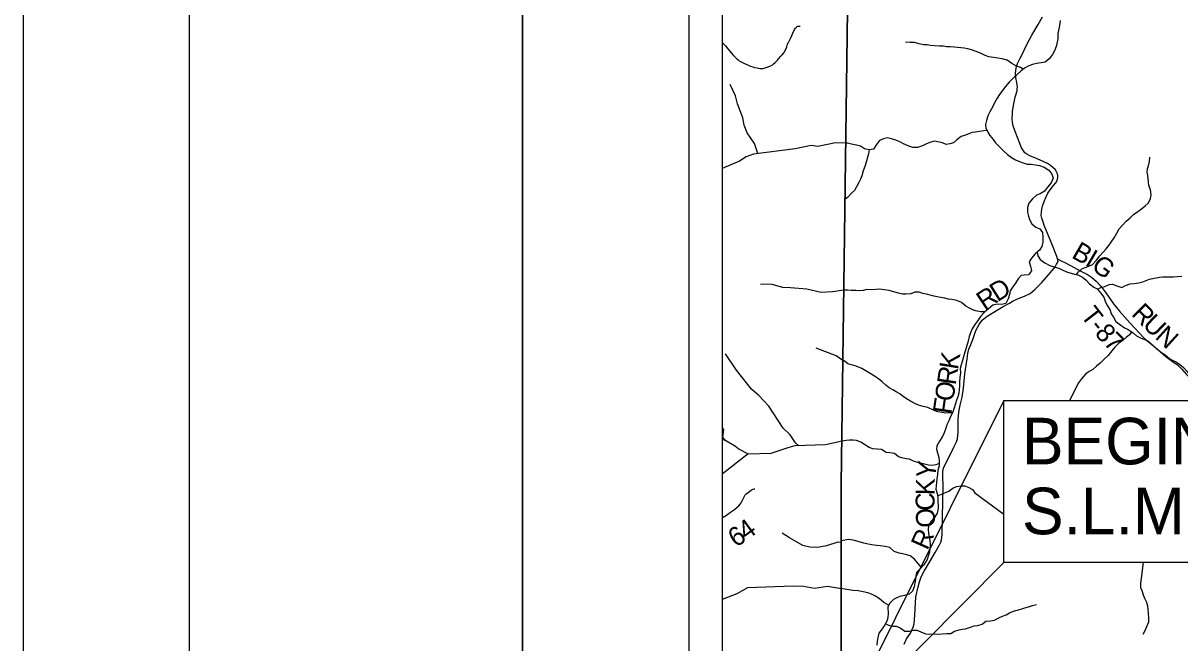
# Model space of a CAD drawing. Extents: x 0 to 34, y 0 to 22.
# Drawn here: x 0 to 3.475, y 18.432 to 20.293 of the extents above; entities that cross this region are included whole.
import ezdxf

# ---------------------------------------------------------------- set-up
doc = ezdxf.new("R2010")
doc.units = 0
for name, color, linetype in [('Default', 7, 'Continuous'), ('GM_X_County_Road', 7, 'Continuous'), ('GM_X_County_Road_Text', 7, 'Continuous'), ('GM_X_Minor_River', 7, 'Continuous'), ('GM_X_Township_Road', 7, 'Continuous'), ('GM_X_Township_Road_Text', 7, 'Continuous'), ('SH_Border', 7, 'Continuous'), ('SH_Cut_Line', 7, 'Continuous'), ('SH_Data', 7, 'Continuous'), ('SH_Text', 7, 'Continuous')]:
    doc.layers.add(name, color=color, linetype=linetype)

msp = doc.modelspace()

# ---------------------------------------------------------------- linework, layer by layer
at = {"layer": 'Default'}
for points in [[(2.4313, 15.0183), (2.4545, 17.2795), (2.4586, 17.7785), (2.4581, 18.1772), (2.4581, 18.1825), (2.4573, 18.9074), (2.4757, 20.2566), (2.4809, 20.6393), (2.4845, 20.9), (2.1, 20.9), (2.1, 14.9328)], [(6.416, 20.9), (2.4845, 20.9), (2.4809, 20.6393), (2.4757, 20.2566), (2.4573, 18.9074), (2.4581, 18.1825), (2.4581, 18.1772), (2.4586, 17.7785), (2.4545, 17.2795), (2.6193, 17.2753), (3.4366, 17.255), (3.467, 17.2465), (3.4629, 17.4891), (3.5442, 17.5398)]]:
    msp.add_lwpolyline(points, dxfattribs=at)
at = {"layer": 'GM_X_County_Road'}
for points in [[(2.9992, 20.1948), (3.0166, 20.2316), (3.0304, 20.257), (3.0492, 20.2896), (3.0625, 20.3124)], [(2.9869, 20.0982), (2.9871, 20.1001), (2.9869, 20.1075), (2.9856, 20.1151), (2.9826, 20.1288), (2.9818, 20.141), (2.9828, 20.1522), (2.9846, 20.1629), (2.9874, 20.1721), (2.9958, 20.1876), (2.9992, 20.1948)], [(2.6466, 18.4282), (2.654, 18.4437), (2.6662, 18.4612), (2.6738, 18.4788), (2.6772, 18.4887), (2.6792, 18.5154), (2.682, 18.5697), (2.6888, 18.5999), (2.6926, 18.6151), (2.6975, 18.6276), (2.7015, 18.6365), (2.7068, 18.6475), (2.7228, 18.674), (2.7397, 18.7033), (2.7529, 18.7265), (2.757, 18.7341), (2.7596, 18.7413), (2.761, 18.7562), (2.7621, 18.8099), (2.7646, 18.8999), (2.7633, 18.9353), (2.7635, 18.9461), (2.7656, 18.9561), (2.769, 18.9658), (2.7791, 18.9848), (2.7966, 19.02), (2.804, 19.0358), (2.8068, 19.0447), (2.8093, 19.0653), (2.8093, 19.0817), (2.8089, 19.1033), (2.8114, 19.1245), (2.8148, 19.1457), (2.8208, 19.17), (2.8251, 19.1965), (2.8295, 19.2395), (2.8359, 19.2848), (2.8386, 19.301), (2.8417, 19.3137), (2.845, 19.3229), (2.853, 19.3428), (2.8628, 19.3703), (2.8722, 19.388), (2.8814, 19.401), (2.8968, 19.4135), (2.9449, 19.4422), (2.9637, 19.4526), (2.9749, 19.4594), (2.9923, 19.4671), (3.0085, 19.4735), (3.0251, 19.4807), (3.0394, 19.4928), (3.0604, 19.5142), (3.0863, 19.5444), (3.1003, 19.5614), (3.1051, 19.5696), (3.1093, 19.5769), (3.108, 19.5852), (3.1059, 19.5921), (3.0907, 19.6302), (3.0688, 19.6833), (3.0606, 19.7072), (3.0591, 19.7153), (3.0594, 19.7252), (3.0606, 19.7346), (3.0627, 19.7435), (3.0672, 19.7573), (3.0726, 19.7697), (3.0787, 19.7822), (3.0858, 19.7926), (3.096, 19.8053), (3.1026, 19.814), (3.1062, 19.8211), (3.1084, 19.8298), (3.109, 19.8353), (3.1077, 19.8409), (3.1051, 19.8468), (3.1013, 19.8529), (3.0937, 19.86), (3.0866, 19.8656), (3.0772, 19.8715), (3.0665, 19.8771), (3.0469, 19.8857), (3.0296, 19.8926), (3.0222, 19.8959), (3.0159, 19.8997), (3.0093, 19.904), (3.0054, 19.9096), (2.9988, 19.9208), (2.9948, 19.9317), (2.9803, 19.9676), (2.9747, 19.9851), (2.9726, 19.9951), (2.9719, 20.0073), (2.9721, 20.0197), (2.9729, 20.0291), (2.9749, 20.0396), (2.9767, 20.0505), (2.981, 20.0706), (2.9861, 20.0904), (2.9869, 20.0982)]]:
    msp.add_lwpolyline(points, dxfattribs=at)
at = {"layer": 'GM_X_Minor_River'}
msp.add_line((2.1783, 18.9994), (2.1, 18.9382), dxfattribs=at)
for points in [[(3.1162, 20.3016), (3.1146, 20.2922), (3.1127, 20.2812), (3.1111, 20.2713), (3.1092, 20.2618), (3.1087, 20.2463), (3.1056, 20.2326), (3.1036, 20.2228), (3.099, 20.2099), (3.0925, 20.1986), (3.0829, 20.1861), (3.0707, 20.1759), (3.0586, 20.1737), (3.0449, 20.1719), (3.0328, 20.169), (3.0199, 20.1645), (3.0081, 20.1585), (2.9971, 20.1495), (2.9875, 20.1404), (2.9749, 20.1283), (2.9624, 20.1159), (2.9517, 20.1034), (2.9414, 20.0895), (2.9333, 20.0789), (2.9265, 20.0679), (2.9188, 20.0543), (2.9123, 20.0407), (2.9046, 20.0271), (2.8988, 20.0146), (2.8942, 20.001), (2.8911, 19.9885), (2.8922, 19.9786), (2.8982, 19.9656), (2.9045, 19.9557), (2.9143, 19.9439), (2.9218, 19.9336), (2.9331, 19.9214), (2.9459, 19.9099), (2.9576, 19.8985), (2.9697, 19.8901), (2.9817, 19.8824), (2.9938, 19.8774), (3.0048, 19.8735), (3.0169, 19.87), (3.0286, 19.87), (3.0415, 19.868), (3.0536, 19.8656), (3.0676, 19.861), (3.0816, 19.8518), (3.091, 19.84), (3.0947, 19.8274), (3.0889, 19.8138), (3.0775, 19.8006), (3.0683, 19.7881), (3.0558, 19.781), (3.0444, 19.7761), (3.0322, 19.7656), (3.0215, 19.7524), (3.0172, 19.7399), (3.0175, 19.7258), (3.0208, 19.7133), (3.0238, 19.703), (3.0306, 19.6908), (3.0422, 19.6809), (3.0547, 19.6751), (3.0626, 19.664), (3.064, 19.65), (3.0632, 19.6356), (3.0608, 19.6227), (3.0532, 19.6114), (3.0402, 19.6004), (3.0292, 19.5872), (3.0226, 19.5759), (3.0267, 19.563), (3.0297, 19.5497), (3.0205, 19.5376), (3.0076, 19.5365), (2.9981, 19.5354), (2.9897, 19.5252), (2.9813, 19.5124), (2.9733, 19.5014), (2.9653, 19.489), (2.9633, 19.4783), (2.9594, 19.4647), (2.9525, 19.4511), (2.9408, 19.4478), (2.9264, 19.449), (2.9138, 19.446), (2.9001, 19.4351), (2.888, 19.4249), (2.8761, 19.4117), (2.8685, 19.4004), (2.8593, 19.3883), (2.8517, 19.3755), (2.8459, 19.3626), (2.8428, 19.352)], [(3.0043, 20.1554), (2.9967, 20.1601), (2.9846, 20.1636), (2.9707, 20.172), (2.9563, 20.1816), (2.9416, 20.1859), (2.9287, 20.1878), (2.9155, 20.1898), (2.9018, 20.1922), (2.8901, 20.1961), (2.8762, 20.203), (2.8633, 20.2084), (2.8497, 20.2134), (2.8387, 20.2161), (2.8274, 20.2181), (2.8171, 20.2193), (2.8073, 20.2201), (2.7971, 20.2209), (2.7857, 20.2221), (2.7747, 20.2226), (2.7638, 20.2238), (2.7528, 20.2242), (2.7384, 20.2247), (2.7263, 20.2263), (2.716, 20.2279), (2.7054, 20.2283), (2.6918, 20.2315), (2.6778, 20.2353), (2.6646, 20.2354), (2.6513, 20.2363)], [(2.2074, 19.9016), (2.1971, 19.9314), (2.1756, 19.9641), (2.1659, 19.9864), (2.1623, 20.0088), (2.1467, 20.0513), (2.1401, 20.0754), (2.1243, 20.1088)], [(2.8959, 19.9704), (2.8861, 19.9695), (2.8747, 19.9677), (2.8614, 19.9659), (2.8512, 19.9644), (2.8417, 19.9611), (2.828, 19.9562), (2.8181, 19.9525), (2.8048, 19.9427), (2.7949, 19.934), (2.7839, 19.9303), (2.7737, 19.9289), (2.7623, 19.9335), (2.7521, 19.9362), (2.7385, 19.9386), (2.7241, 19.9349), (2.7119, 19.9296), (2.7024, 19.9248), (2.6868, 19.9195), (2.6728, 19.92), (2.6607, 19.9239), (2.6448, 19.9304), (2.6343, 19.9366), (2.6222, 19.942), (2.6089, 19.9458), (2.5965, 19.9486), (2.5851, 19.946), (2.5729, 19.9408), (2.5638, 19.9283), (2.555, 19.9151), (2.5405, 19.9129), (2.5281, 19.916), (2.5156, 19.9233), (2.5043, 19.9264), (2.4891, 19.9299), (2.477, 19.9326), (2.4721, 19.9328)], [(2.4721, 19.9328), (2.4408, 19.9338), (2.3875, 19.9226), (2.3672, 19.9254), (2.3197, 19.9155), (2.1941, 19.9), (2.1723, 19.8921), (2.1523, 19.8782), (2.1, 19.8563)], [(2.5421, 19.9131), (2.5401, 19.9004), (2.5355, 19.8867), (2.5327, 19.8757), (2.5285, 19.8629), (2.5239, 19.8496), (2.5196, 19.8348), (2.5157, 19.825), (2.5111, 19.8148), (2.4973, 19.791), (2.4882, 19.7811), (2.4768, 19.7698), (2.4698, 19.7646)], [(3.1648, 19.5381), (3.171, 19.5465), (3.1809, 19.5555), (3.1904, 19.5593), (3.2022, 19.5637), (3.2124, 19.5686), (3.2246, 19.5818), (3.2353, 19.5946), (3.2441, 19.6048), (3.254, 19.615), (3.262, 19.6252), (3.2693, 19.635), (3.2781, 19.6486), (3.2861, 19.6623), (3.293, 19.6751), (3.3026, 19.6868), (3.3144, 19.6985), (3.3262, 19.7083), (3.3357, 19.7181), (3.3491, 19.7279), (3.3601, 19.7358), (3.3707, 19.7441), (3.3806, 19.7524), (3.3876, 19.7652), (3.3888, 19.7777), (3.387, 19.7922), (3.3825, 19.8055), (3.3807, 19.8157), (3.38, 19.8264), (3.3793, 19.8359), (3.3774, 19.8457), (3.3783, 19.8552), (3.3814, 19.8651), (3.3841, 19.8776), (3.3849, 19.8905)], [(3.047, 19.6061), (3.0489, 19.5943), (3.0553, 19.5836), (3.0696, 19.5737), (3.0851, 19.5656), (3.1006, 19.5602), (3.1116, 19.5575), (3.1233, 19.551), (3.1373, 19.5452), (3.1486, 19.5421), (3.1584, 19.5397), (3.169, 19.537), (3.183, 19.5305), (3.1939, 19.5209), (3.2037, 19.5098), (3.2165, 19.5007), (3.2264, 19.4953), (3.2365, 19.4827), (3.2474, 19.4697), (3.2522, 19.4553), (3.2582, 19.4442), (3.2657, 19.4313), (3.2691, 19.4206), (3.2755, 19.4103), (3.2829, 19.3966), (3.2977, 19.3859), (3.3094, 19.3779), (3.3199, 19.3729), (3.3346, 19.3629), (3.3452, 19.3537), (3.3573, 19.348), (3.3694, 19.3433), (3.3792, 19.3387), (3.3958, 19.3238), (3.406, 19.3154), (3.4192, 19.3051), (3.432, 19.2963), (3.4444, 19.2856), (3.4542, 19.2796)], [(3.2275, 19.4939), (3.2377, 19.499), (3.2495, 19.5023), (3.2632, 19.5083), (3.2727, 19.5094), (3.2863, 19.5044), (3.3006, 19.4994), (3.312, 19.505), (3.3261, 19.5098), (3.3382, 19.5113), (3.3523, 19.5131), (3.364, 19.5164), (3.3743, 19.5201), (3.3841, 19.5239), (3.394, 19.5265), (3.4043, 19.5279), (3.4137, 19.5301), (3.4236, 19.5308), (3.4331, 19.5312), (3.4563, 19.5315)], [(3.4563, 19.5315), (3.4672, 19.5318), (3.4813, 19.5336)], [(2.4661, 19.4907), (2.4319, 19.4861), (2.3979, 19.4838), (2.3547, 19.494), (2.3056, 19.4982), (2.2822, 19.4988), (2.2506, 19.5083), (2.2155, 19.5095)], [(2.8889, 19.4257), (2.877, 19.4265), (2.8664, 19.4281), (2.8554, 19.4308), (2.8429, 19.437), (2.832, 19.4431), (2.8188, 19.4538), (2.8052, 19.46), (2.7904, 19.4631), (2.7806, 19.4639), (2.7689, 19.4667), (2.7575, 19.4694), (2.7458, 19.471), (2.7325, 19.4745), (2.7178, 19.4784), (2.703, 19.4815), (2.6921, 19.485), (2.6792, 19.4847), (2.667, 19.4798), (2.6519, 19.4788), (2.642, 19.4789), (2.6295, 19.4824), (2.6189, 19.4855), (2.6015, 19.4897), (2.5868, 19.4917), (2.5728, 19.4945), (2.5622, 19.493), (2.5485, 19.4924), (2.5345, 19.4928), (2.5235, 19.4902), (2.5136, 19.4892), (2.5019, 19.49), (2.4879, 19.4905), (2.478, 19.4909), (2.4661, 19.4907)], [(3.3305, 19.3657), (3.324, 19.3569), (3.3145, 19.3494), (3.305, 19.3411), (3.2905, 19.3306), (3.2798, 19.32), (3.2707, 19.3094), (3.26, 19.2947), (3.2459, 19.2815), (3.2356, 19.2721), (3.2245, 19.2627), (3.2139, 19.2532), (3.2024, 19.2465), (3.1918, 19.2386), (3.1796, 19.225), (3.1712, 19.2125), (3.1442, 19.1594)], [(2.8428, 19.352), (2.8389, 19.3376), (2.8366, 19.3281), (2.8289, 19.3054), (2.825, 19.2914), (2.8226, 19.28), (2.8184, 19.2667), (2.8157, 19.2558), (2.816, 19.2429), (2.8144, 19.2284), (2.8128, 19.2155), (2.8131, 19.2049), (2.8126, 19.1916), (2.8114, 19.1818), (2.8083, 19.1712), (2.8045, 19.1606), (2.8014, 19.1507), (2.7975, 19.1378), (2.7921, 19.1231), (2.7867, 19.1114), (2.781, 19.0985), (2.7756, 19.0868), (2.7721, 19.0769), (2.7671, 19.0629), (2.7617, 19.0519), (2.7529, 19.0379), (2.7453, 19.024), (2.7441, 19.0133), (2.7474, 19.0023), (2.7511, 18.9886), (2.7525, 18.9768), (2.7521, 18.9632), (2.7486, 18.9503), (2.747, 18.937), (2.7454, 18.9245), (2.7438, 18.9135), (2.743, 18.9033), (2.7426, 18.8938), (2.7459, 18.8805), (2.7477, 18.8699), (2.7484, 18.8558), (2.7494, 18.8452), (2.7494, 18.8349), (2.7459, 18.8209), (2.7386, 18.8088), (2.7276, 18.7964), (2.7199, 18.7824), (2.7187, 18.7729), (2.7201, 18.7604), (2.722, 18.7505), (2.7238, 18.738), (2.7248, 18.7258), (2.724, 18.7144), (2.7228, 18.7046), (2.7193, 18.6921), (2.7158, 18.6818), (2.7063, 18.666), (2.6952, 18.6546), (2.6845, 18.6433), (2.6822, 18.6331), (2.6806, 18.6221), (2.6794, 18.6122), (2.6774, 18.6005), (2.6724, 18.5872), (2.6618, 18.5778), (2.6481, 18.5745), (2.6341, 18.5712), (2.6246, 18.5667), (2.6151, 18.5618), (2.6029, 18.5505), (2.5975, 18.5388), (2.5989, 18.519), (2.5981, 18.5088), (2.5957, 18.4993), (2.5892, 18.4864), (2.5808, 18.474), (2.5712, 18.4604), (2.5678, 18.4482), (2.5654, 18.4361), (2.5653, 18.4251)], [(2.3303, 19.0238), (2.3206, 19.0328), (2.3049, 19.0563), (2.2839, 19.0769), (2.2405, 19.1424), (2.2106, 19.1747), (2.1888, 19.1938), (2.1429, 19.2506), (2.1101, 19.3)], [(2.4632, 19.2804), (2.4428, 19.2938), (2.3825, 19.3173)], [(2.7919, 19.1226), (2.7845, 19.1228), (2.7713, 19.1217), (2.7614, 19.1233), (2.7482, 19.126), (2.7349, 19.1303), (2.7179, 19.1384), (2.7036, 19.1422), (2.6903, 19.1457), (2.679, 19.1504), (2.6658, 19.158), (2.6541, 19.1649), (2.6443, 19.1722), (2.6341, 19.1795), (2.6231, 19.1856), (2.6129, 19.1914), (2.6016, 19.1983), (2.5918, 19.2063), (2.5809, 19.2155), (2.5703, 19.2251), (2.5579, 19.2331), (2.5451, 19.2411), (2.5352, 19.2473), (2.5194, 19.2561), (2.5028, 19.2627), (2.4891, 19.2669), (2.4782, 19.2704), (2.4669, 19.2785), (2.4632, 19.2804)], [(3.4542, 19.2796), (3.4621, 19.2766), (3.4753, 19.2677), (3.4859, 19.2593), (3.4964, 19.2475), (3.5062, 19.2337), (3.5186, 19.2207), (3.5835, 19.1594)], [(2.1101, 19.0389), (2.102, 19.0498), (2.1049, 19.0718), (2.1, 19.0793)], [(2.4604, 19.0375), (2.4105, 19.0268), (2.3189, 19.0233), (2.2972, 19.0174), (2.2465, 19.0004), (2.1798, 18.9986), (2.1499, 19.0134), (2.1403, 19.0216), (2.1079, 19.0402), (2.1, 19.0414)], [(2.7523, 18.9707), (2.7423, 18.967), (2.7316, 18.9641), (2.7206, 18.9653), (2.704, 18.9692), (2.6881, 18.9735), (2.6753, 18.9773), (2.6632, 18.9831), (2.6526, 18.9847), (2.6405, 18.9874), (2.6299, 18.9909), (2.6178, 19.0005), (2.6038, 19.0021), (2.5932, 19.0037), (2.5789, 19.0121), (2.5667, 19.0137), (2.5524, 19.0142), (2.5414, 19.0184), (2.5305, 19.0261), (2.5172, 19.0349), (2.5036, 19.0395), (2.4934, 19.0403), (2.4828, 19.0404), (2.4726, 19.0397), (2.4604, 19.0375), (2.4599, 19.0374)], [(2.7471, 18.8735), (2.7568, 18.877), (2.7663, 18.8811), (2.7812, 18.8879), (2.7937, 18.8969), (2.804, 18.9014), (2.8169, 18.9036), (2.8279, 18.9031), (2.8396, 18.8993), (2.8524, 18.892), (2.8596, 18.8824), (2.9469, 18.818)], [(2.4583, 18.7335), (2.4476, 18.7346), (2.414, 18.7233), (2.3871, 18.7186), (2.364, 18.7192), (2.3429, 18.7242), (2.3026, 18.7468), (2.2807, 18.761)], [(2.699, 18.6585), (2.6881, 18.6714), (2.6783, 18.6828), (2.6648, 18.6932), (2.6549, 18.6966), (2.6425, 18.6994), (2.6315, 18.701), (2.6167, 18.7064), (2.6039, 18.7182), (2.5899, 18.7213), (2.5748, 18.7237), (2.5646, 18.7245), (2.5498, 18.7265), (2.5392, 18.7285), (2.526, 18.7309), (2.5157, 18.7343), (2.5048, 18.7371), (2.4934, 18.7402), (2.4798, 18.7421), (2.4639, 18.7396), (2.4583, 18.7382)], [(3.3646, 18.673), (3.3572, 18.6102), (3.3575, 18.5985), (3.3609, 18.5886), (3.3653, 18.5764), (3.3694, 18.5658), (3.3747, 18.5536), (3.3784, 18.5429), (3.3787, 18.5334), (3.3802, 18.5209), (3.3808, 18.5069), (3.3807, 18.494), (3.375, 18.4803), (3.3696, 18.4678), (3.3638, 18.4565)], [(2.4585, 18.5938), (2.4163, 18.6011), (2.378, 18.5952), (2.3448, 18.6009), (2.3135, 18.6024), (2.1764, 18.597), (2.1438, 18.5792), (2.1, 18.5616)], [(2.6002, 18.5446), (2.5858, 18.5529), (2.5715, 18.5647), (2.5591, 18.5735), (2.5489, 18.5785), (2.5379, 18.582), (2.5235, 18.5855), (2.5088, 18.5883), (2.4932, 18.5895), (2.4808, 18.5915), (2.4679, 18.5935), (2.4585, 18.5953)], [(2.5906, 18.4892), (2.6006, 18.4845), (2.6127, 18.4821), (2.6225, 18.4821), (2.6346, 18.4767), (2.6493, 18.4667), (2.6634, 18.4674), (2.6747, 18.4696), (2.685, 18.4703), (2.6974, 18.4645), (2.7114, 18.4591), (2.7213, 18.4575), (2.7379, 18.4589), (2.7504, 18.4581), (2.7607, 18.4592), (2.7751, 18.4602), (2.7868, 18.4601), (2.7986, 18.4673), (2.8119, 18.4714), (2.8221, 18.4728), (2.8316, 18.4739), (2.8464, 18.4791), (2.8571, 18.4828), (2.8673, 18.4839), (2.8813, 18.488), (2.8928, 18.4974), (2.906, 18.4981), (2.9182, 18.4999), (2.9318, 18.5067), (2.9421, 18.5119), (2.9531, 18.5164), (2.963, 18.5216), (2.9759, 18.5269), (2.9866, 18.5298), (3.0002, 18.5343), (3.0097, 18.5369), (3.0203, 18.5403), (3.0321, 18.5436), (3.045, 18.5469)]]:
    msp.add_lwpolyline(points, dxfattribs=at)
at = {"layer": 'GM_X_Township_Road'}
for points in [[(2.1, 20.2349), (2.1046, 20.2307), (2.1098, 20.2253), (2.1175, 20.2164), (2.1336, 20.1967), (2.1382, 20.1916), (2.143, 20.1868), (2.1468, 20.1837), (2.1515, 20.1805), (2.1557, 20.1781), (2.159, 20.1762), (2.1651, 20.1732), (2.1764, 20.168), (2.185, 20.1644), (2.1926, 20.1617), (2.1974, 20.1603), (2.2053, 20.1586), (2.2138, 20.1575), (2.2182, 20.1573), (2.2219, 20.1575), (2.2268, 20.1583), (2.2328, 20.1598), (2.2387, 20.1619), (2.2455, 20.1648), (2.2504, 20.1674), (2.2549, 20.1707), (2.2581, 20.1737), (2.266, 20.1825), (2.2695, 20.1861), (2.2766, 20.1938), (2.2806, 20.1985), (2.286, 20.2054), (2.2889, 20.2094), (2.29, 20.2116), (2.2914, 20.2151), (2.2943, 20.2225), (2.2966, 20.2297), (2.299, 20.2347), (2.3006, 20.2373), (2.3067, 20.2488), (2.3129, 20.2628), (2.3178, 20.2742), (2.3196, 20.2774), (2.321, 20.2794), (2.3232, 20.2816), (2.3253, 20.283), (2.3275, 20.2841), (2.3293, 20.2845), (2.331, 20.2846), (2.3326, 20.2844), (2.3339, 20.2838), (2.3347, 20.2829)], [(3.108, 19.5852), (3.1171, 19.5808), (3.1313, 19.5736), (3.1822, 19.5459), (3.1977, 19.5378), (3.2094, 19.5302), (3.2239, 19.5185), (3.2376, 19.5035), (3.2529, 19.4834), (3.2763, 19.4498), (3.2941, 19.4277), (3.3246, 19.3933), (3.3684, 19.3473), (3.4093, 19.3132), (3.433, 19.2921), (3.4559, 19.2746), (3.4686, 19.2672), (3.4808, 19.2542), (3.495, 19.2374), (3.5161, 19.2168), (3.5906, 19.1594)], [(2.1, 18.8075), (2.1011, 18.8081), (2.1131, 18.8158), (2.1254, 18.8243), (2.1369, 18.8328), (2.1452, 18.8393), (2.1498, 18.8434), (2.154, 18.8479), (2.1569, 18.8519), (2.1597, 18.8568), (2.1631, 18.8641), (2.1662, 18.8709), (2.168, 18.8741), (2.1695, 18.8761), (2.1717, 18.8783), (2.1758, 18.8819), (2.1825, 18.8868), (2.1885, 18.8912), (2.1911, 18.8926), (2.1935, 18.8936), (2.1959, 18.8944), (2.1987, 18.8949)]]:
    msp.add_lwpolyline(points, dxfattribs=at)
at = {"layer": 'SH_Border'}
for points in [[(0.5, 21.5), (1.5, 21.5), (1.5, 0.5), (0.5, 0.5)], [(1.5, 21.5), (33.5, 21.5), (33.5, 0.5), (1.5, 0.5)]]:
    msp.add_lwpolyline(points, close=True, dxfattribs=at)
at = {"layer": 'SH_Cut_Line'}
for points in [[(0, 0), (34, 0), (34, 22), (0, 22)], [(2.4845, 20.9), (2.1, 20.9), (2.1, 14.1), (2.4352, 14.1), (2.4372, 14.2719), (2.4313, 15.0183), (2.4545, 17.2795), (2.4586, 17.7785), (2.4581, 18.1772), (2.4581, 18.1825), (2.4573, 18.9074), (2.4757, 20.2566), (2.4809, 20.6393)], [(2.4352, 14.1), (8.9, 14.1), (8.9, 20.9), (2.4845, 20.9), (2.4809, 20.6393), (2.4757, 20.2566), (2.4573, 18.9074), (2.4581, 18.1825), (2.4581, 18.1772), (2.4586, 17.7785), (2.4545, 17.2795), (2.4313, 15.0183), (2.4372, 14.2719)]]:
    msp.add_lwpolyline(points, close=True, dxfattribs=at)
at = {"layer": 'SH_Data'}
for p, q in [((2, 21), (2, 14)), ((2.1, 20.9), (2.1, 14.1))]:
    msp.add_line(p, q, dxfattribs=at)
at = {"layer": 'SH_Text'}
for points in [[(2.9469, 19.1594), (2.4583, 18.1819), (2.9469, 18.673)], [(2.9469, 19.1594), (4.4427, 19.1594), (4.4427, 18.673), (2.9469, 18.673)]]:
    msp.add_lwpolyline(points, close=True, dxfattribs=at)

# ---------------------------------------------------------------- texts
at = {"layer": 'GM_X_County_Road_Text'}
for s, rotation, p in [('R', 33.5309, (2.8885, 19.4289)), ('D', 32.2027, (2.9271, 19.4545)), ('K', 80.9596, (2.8083, 19.2503)), ('R', 81.6593, (2.8015, 19.2043)), ('O', 81.6754, (2.7943, 19.1548)), ('F', 81.6747, (2.7887, 19.1169)), ('Y', 81.8014, (2.739, 18.923)), ('K', 89.1913, (2.7385, 18.8749)), ('C', 89.4282, (2.738, 18.8283)), ('O', 93.69, (2.7412, 18.7796)), ('R', 65.7282, (2.7166, 18.7075))]:
    msp.add_text(s, height=0.0568, rotation=rotation, dxfattribs=at).set_placement(p)
at = {"layer": 'GM_X_Township_Road_Text'}
for s, rotation, p in [('B', 330.032, (3.147, 19.5905)), ('I', 329.5938, (3.1874, 19.5673)), ('G', 323.3272, (3.2061, 19.5564)), ('T', 307.9915, (3.1747, 19.4147)), ('R', 315.316, (3.3269, 19.4173)), ('-', 308.6272, (3.2013, 19.3806)), ('U', 315.8731, (3.3605, 19.3841)), ('8', 310.6263, (3.2173, 19.3607)), ('7', 315.0045, (3.2433, 19.3307)), ('N', 317.8427, (3.3979, 19.3479)), ('4', 35.87, (2.1733, 18.738)), ('6', 33.1607, (2.1415, 18.7172))]:
    msp.add_text(s, height=0.0568, rotation=rotation, dxfattribs=at).set_placement(p)
at = {"layer": 'SH_Text'}
for s, p in [('BEGIN PROJECT', (3.0011, 18.9679)), ('S.L.M.  0.00', (3.0011, 18.7579))]:
    msp.add_text(s, height=0.14, dxfattribs=at).set_placement(p)

doc.saveas('drawing.dxf')
